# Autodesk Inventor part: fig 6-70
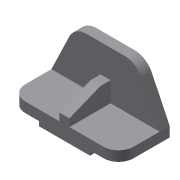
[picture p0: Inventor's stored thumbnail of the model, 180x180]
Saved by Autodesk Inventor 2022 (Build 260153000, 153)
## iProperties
Created: 2001-12
Part Number: fig 6-70
Document SubType Name: Modeling
Designer: Renu Muthoo
Density: 1 g/cm^3
Material: Generic
Appearance: Default
Control State: 0
Master: False
Checked Out: False
Shininess: 77.0
Length Units: 11269
Angle Units: 11279
Time Units: 11290
Mass Units: 11283
Length Display Precision: 3
Angle Display Precision: 2
Density: 0.0
Volumn: 0.0
Area: 0.0
PropertySet Name: Model Information
Author: Renu Muthoo
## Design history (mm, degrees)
sketch "Sketch2"
  geometry: L1 (-67.219, 19.116)-(148.781, 19.116); L2 (148.781, 19.116)-(148.781, -0.884); L3 (-67.219, -0.884)-(-67.219, 19.116); L4 (-10.219, -0.884)-(-10.219, -9.884); L5 (-10.219, -9.884)-(91.781, -9.884); L6 (91.781, -9.884)-(91.781, -0.884); L7 (148.781, -0.884)-(91.781, -0.884); L8 (-10.219, -0.884)-(-67.219, -0.884)
  constraints: 16 end point, 5 parallel, 4 perpendicular, 2 equal length, 1 horizontal
  dimensions: "d0" = 102 distance of L4.end L5.end; "d1" = 57 distance of L4.start L3.start; "d2" = 29 distance between parallel lines of L1 L5; "d3" = 20 distance of L1.end L2.end
extrude "Extrusion1" new body sketch "Sketch2" distance "d4" = 102; taper "d5" = 0 deg
sketch "Sketch3"
  geometry: L1 (67.219, -19.116)-(-148.781, -19.116) reference; L2 (67.219, -19.116)-(31.475, -93.564); L3 (-2.781, -115.116)-(-78.781, -115.116); L4 (-113.038, -93.564)-(-148.781, -19.116); A1 r 38 centre (-2.781, -77.116) between (-2.781, -115.116) and (31.475, -93.564); A2 r 38 centre (-78.781, -77.116) between (-113.038, -93.564) and (-78.781, -115.116)
  constraints: 6 end point, 4 point on circle, 4 tangent, 2 centre point, 1 equal length, 1 equal radius, 1 parallel
  dimensions: "d6" = 96 distance between parallel lines of L3 L1; "d7" = 38 radius of A1; "d8" = 76 distance of A2.centre A1.centre
extrude "Extrusion2" join sketch "Sketch3" distance "d9" = 20; taper "d10" = 0 deg
fillet "Fillet1" dims "d11" = 30
workplane "Work Plane1"
sketch "Sketch7"
  geometry: L1 (0, -82)-(-15, -82); L2 (-15, -82)-(-40, -20); L3 (-40, -20)-(-40, 0); L4 (0, -82)-(20, -82) reference; L5 (0, 0)-(-74.447, 0) reference
  constraints: 6 end point, 2 point on line, 1 horizontal, 1 perpendicular
  dimensions: "d32" = 20 distance of L2.end L3.end; "d33" = 15 distance of L1.start L1.end; "d34" = 40 distance of L5.start L3.end
feature "Rib4" sketch "Sketch7" dims "d55" = 1, "d56" = 20, "d57" = 0
body "Solid1"
other parameters: "d12" = -108
